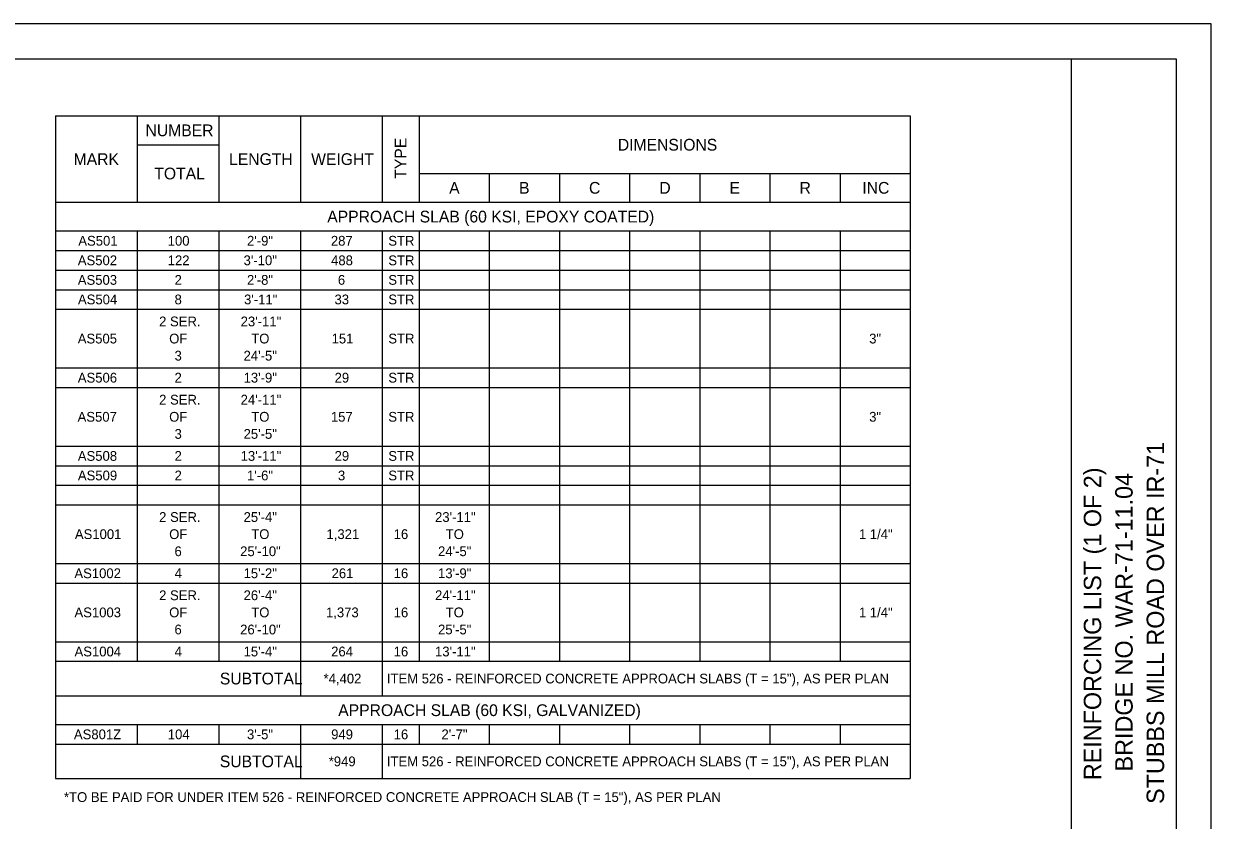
# Model space of a CAD drawing. Extents: x 0 to 34, y 0 to 22.
# Drawn here: x 17 to 34, y 10.6 to 22 of the extents above; entities that cross this region are included whole.
import ezdxf

# ---------------------------------------------------------------- set-up
doc = ezdxf.new("R2010")
doc.units = 0
for name, color, linetype in [('Default', 7, 'Continuous'), ('SH_Border', 7, 'Continuous'), ('SH_Cut_Line', 7, 'Continuous'), ('SH_Data', 7, 'Continuous'), ('SH_Text', 7, 'Continuous')]:
    doc.layers.add(name, color=color, linetype=linetype)

msp = doc.modelspace()

# ---------------------------------------------------------------- linework, layer by layer
at = {"layer": 'SH_Border'}
msp.add_line((32, 0.5), (32, 21.5), dxfattribs=at)
msp.add_lwpolyline([(1.5, 21.5), (33.5, 21.5), (33.5, 0.5), (1.5, 0.5)], close=True, dxfattribs=at)
at = {"layer": 'SH_Cut_Line'}
msp.add_lwpolyline([(0, 0), (34, 0), (34, 22), (0, 22)], close=True, dxfattribs=at)
at = {"layer": 'SH_Text'}
for p, q in [((17.454, 20.68), (29.692, 20.68)), ((17.454, 20.68), (17.454, 11.193)), ((18.624, 20.68), (18.624, 19.445)), ((19.793, 20.68), (19.793, 19.445)), ((20.962, 20.68), (20.962, 19.445)), ((22.132, 20.68), (22.132, 19.445)), ((22.659, 20.68), (22.659, 19.445)), ((29.692, 20.68), (29.692, 11.193)), ((18.624, 20.268), (19.793, 20.268)), ((22.659, 19.856), (29.692, 19.856)), ((23.664, 19.856), (23.664, 19.445)), ((24.668, 19.856), (24.668, 19.445)), ((25.673, 19.856), (25.673, 19.445)), ((26.678, 19.856), (26.678, 19.445)), ((27.682, 19.856), (27.682, 19.445)), ((28.687, 19.856), (28.687, 19.445)), ((17.454, 19.445), (29.692, 19.445)), ((17.454, 19.033), (29.692, 19.033)), ((18.624, 19.033), (18.624, 12.873)), ((19.793, 19.033), (19.793, 12.873)), ((20.962, 19.033), (20.962, 12.379)), ((22.132, 19.033), (22.132, 12.379)), ((22.659, 19.033), (22.659, 12.873)), ((23.664, 19.033), (23.664, 12.873)), ((24.668, 19.033), (24.668, 12.873)), ((25.673, 19.033), (25.673, 12.873)), ((26.678, 19.033), (26.678, 12.873)), ((27.682, 19.033), (27.682, 12.873)), ((28.687, 19.033), (28.687, 12.873)), ((17.454, 18.753), (29.692, 18.753)), ((17.454, 18.473), (29.692, 18.473)), ((17.454, 18.193), (29.692, 18.193)), ((17.454, 17.913), (29.692, 17.913)), ((17.454, 17.073), (29.692, 17.073)), ((17.454, 16.793), (29.692, 16.793)), ((17.454, 15.953), (29.692, 15.953)), ((17.454, 15.673), (29.692, 15.673)), ((17.454, 15.393), (29.692, 15.393)), ((17.454, 15.113), (29.692, 15.113)), ((17.454, 14.273), (29.692, 14.273)), ((17.454, 13.993), (29.692, 13.993)), ((17.454, 13.153), (29.692, 13.153)), ((17.454, 12.873), (29.692, 12.873)), ((17.454, 12.379), (29.692, 12.379)), ((17.454, 11.967), (29.692, 11.967)), ((18.624, 11.967), (18.624, 11.687)), ((19.793, 11.967), (19.793, 11.687)), ((20.962, 11.967), (20.962, 11.193)), ((22.132, 11.967), (22.132, 11.193)), ((22.659, 11.967), (22.659, 11.687)), ((23.664, 11.967), (23.664, 11.687)), ((24.668, 11.967), (24.668, 11.687)), ((25.673, 11.967), (25.673, 11.687)), ((26.678, 11.967), (26.678, 11.687)), ((27.682, 11.967), (27.682, 11.687)), ((28.687, 11.967), (28.687, 11.687)), ((17.454, 11.687), (29.692, 11.687)), ((17.454, 11.193), (29.692, 11.193))]:
    msp.add_line(p, q, dxfattribs=at)

# ---------------------------------------------------------------- texts
at = {"layer": 'Default'}
msp.add_text('*TO BE PAID FOR UNDER ITEM 526 - REINFORCED CONCRETE APPROACH SLAB (T = 15"), AS PER PLAN', height=0.14, dxfattribs=at).set_placement((17.576, 10.859))
at = {"layer": 'SH_Data'}
for s, p in [('STUBBS MILL ROAD OVER IR-71', (33.325, 10.831)), ('REINFORCING LIST (1 OF 2)', (32.425, 11.171)), ('BRIDGE NO. WAR-71-11.04', (32.875, 11.296))]:
    msp.add_text(s, height=0.25, rotation=90, dxfattribs=at).set_placement(p)
at = {"layer": 'SH_Text'}
for s, height, p in [('NUMBER', 0.168, (18.743, 20.39)), ('DIMENSIONS', 0.168, (25.505, 20.184)), ('MARK', 0.168, (17.714, 19.978)), ('LENGTH', 0.168, (19.939, 19.978)), ('WEIGHT', 0.168, (21.114, 19.978)), ('TOTAL', 0.168, (18.869, 19.772)), ('A', 0.168, (23.09, 19.567)), ('B', 0.168, (24.091, 19.567)), ('C', 0.168, (25.092, 19.567)), ('D', 0.168, (26.099, 19.567)), ('E', 0.168, (27.104, 19.567)), ('R', 0.168, (28.106, 19.567)), ('INC', 0.168, (29.005, 19.567)), ('APPROACH SLAB (60 KSI, EPOXY COATED)', 0.168, (21.345, 19.155)), ('AS501', 0.14, (17.781, 18.823)), ('100', 0.14, (19.061, 18.823)), ('2\'-9"', 0.14, (20.196, 18.823)), ('287', 0.14, (21.397, 18.823)), ('STR', 0.14, (22.219, 18.823)), ('AS502', 0.14, (17.774, 18.543)), ('122', 0.14, (19.061, 18.543)), ('3\'-10"', 0.14, (20.147, 18.543)), ('488', 0.14, (21.4, 18.543)), ('STR', 0.14, (22.219, 18.543)), ('AS503', 0.14, (17.774, 18.263)), ('2', 0.14, (19.159, 18.263)), ('2\'-8"', 0.14, (20.196, 18.263)), ('6', 0.14, (21.497, 18.263)), ('STR', 0.14, (22.219, 18.263)), ('AS504', 0.14, (17.776, 17.983)), ('8', 0.14, (19.159, 17.983)), ('3\'-11"', 0.14, (20.154, 17.983)), ('33', 0.14, (21.449, 17.983)), ('STR', 0.14, (22.219, 17.983)), ('2 SER.', 0.14, (18.938, 17.668)), ('23\'-11"', 0.14, (20.105, 17.668)), ('AS505', 0.14, (17.773, 17.423)), ('OF', 0.14, (19.082, 17.423)), ('TO', 0.14, (20.257, 17.423)), ('151', 0.14, (21.407, 17.423)), ('STR', 0.14, (22.219, 17.423)), ('3"', 0.14, (29.103, 17.423)), ('3', 0.14, (19.159, 17.178)), ('24\'-5"', 0.14, (20.147, 17.178)), ('AS506', 0.14, (17.774, 16.863)), ('2', 0.14, (19.159, 16.863)), ('13\'-9"', 0.14, (20.147, 16.863)), ('29', 0.14, (21.45, 16.863)), ('STR', 0.14, (22.219, 16.863)), ('2 SER.', 0.14, (18.938, 16.548)), ('24\'-11"', 0.14, (20.105, 16.548)), ('AS507', 0.14, (17.771, 16.303)), ('OF', 0.14, (19.082, 16.303)), ('TO', 0.14, (20.257, 16.303)), ('157', 0.14, (21.397, 16.303)), ('STR', 0.14, (22.219, 16.303)), ('3"', 0.14, (29.103, 16.303)), ('3', 0.14, (19.159, 16.058)), ('25\'-5"', 0.14, (20.147, 16.058)), ('AS508', 0.14, (17.774, 15.743)), ('2', 0.14, (19.159, 15.743)), ('13\'-11"', 0.14, (20.105, 15.743)), ('29', 0.14, (21.45, 15.743)), ('STR', 0.14, (22.219, 15.743)), ('AS509', 0.14, (17.775, 15.463)), ('2', 0.14, (19.159, 15.463)), ('1\'-6"', 0.14, (20.196, 15.463)), ('3', 0.14, (21.498, 15.463)), ('STR', 0.14, (22.219, 15.463)), ('2 SER.', 0.14, (18.938, 14.868)), ('25\'-4"', 0.14, (20.147, 14.868)), ('23\'-11"', 0.14, (22.888, 14.868)), ('AS1001', 0.14, (17.732, 14.623)), ('OF', 0.14, (19.082, 14.623)), ('TO', 0.14, (20.257, 14.623)), ('1,321', 0.14, (21.334, 14.623)), ('16', 0.14, (22.296, 14.623)), ('TO', 0.14, (23.041, 14.623)), ('1 1/4"', 0.14, (28.956, 14.623)), ('6', 0.14, (19.158, 14.378)), ('25\'-10"', 0.14, (20.098, 14.378)), ('24\'-5"', 0.14, (22.931, 14.378)), ('AS1002', 0.14, (17.725, 14.063)), ('4', 0.14, (19.16, 14.063)), ('15\'-2"', 0.14, (20.147, 14.063)), ('261', 0.14, (21.407, 14.063)), ('16', 0.14, (22.296, 14.063)), ('13\'-9"', 0.14, (22.931, 14.063)), ('2 SER.', 0.14, (18.938, 13.748)), ('26\'-4"', 0.14, (20.147, 13.748)), ('24\'-11"', 0.14, (22.888, 13.748)), ('AS1003', 0.14, (17.726, 13.503)), ('OF', 0.14, (19.082, 13.503)), ('TO', 0.14, (20.257, 13.503)), ('1,373', 0.14, (21.327, 13.503)), ('16', 0.14, (22.296, 13.503)), ('TO', 0.14, (23.041, 13.503)), ('1 1/4"', 0.14, (28.956, 13.503)), ('6', 0.14, (19.158, 13.258)), ('26\'-10"', 0.14, (20.098, 13.258)), ('25\'-5"', 0.14, (22.931, 13.258)), ('AS1004', 0.14, (17.727, 12.943)), ('4', 0.14, (19.16, 12.943)), ('15\'-4"', 0.14, (20.147, 12.943)), ('264', 0.14, (21.401, 12.943)), ('16', 0.14, (22.296, 12.943)), ('13\'-11"', 0.14, (22.888, 12.943)), ('SUBTOTAL', 0.168, (19.807, 12.542)), ('*4,402', 0.14, (21.292, 12.556)), ('ITEM 526 - REINFORCED CONCRETE APPROACH SLABS (T = 15"), AS PER PLAN', 0.14, (22.198, 12.556)), ('APPROACH SLAB (60 KSI, GALVANIZED)', 0.168, (21.502, 12.089)), ('AS801Z', 0.14, (17.718, 11.757)), ('104', 0.14, (19.062, 11.757)), ('3\'-5"', 0.14, (20.196, 11.757)), ('949', 0.14, (21.401, 11.757)), ('16', 0.14, (22.296, 11.757)), ('2\'-7"', 0.14, (22.98, 11.757)), ('SUBTOTAL', 0.168, (19.807, 11.356)), ('*949', 0.14, (21.366, 11.37)), ('ITEM 526 - REINFORCED CONCRETE APPROACH SLABS (T = 15"), AS PER PLAN', 0.14, (22.198, 11.37))]:
    msp.add_text(s, height=height, dxfattribs=at).set_placement(p)
msp.add_text('TYPE', height=0.168, rotation=90, dxfattribs=at).set_placement((22.479, 19.781))

doc.saveas('drawing.dxf')
